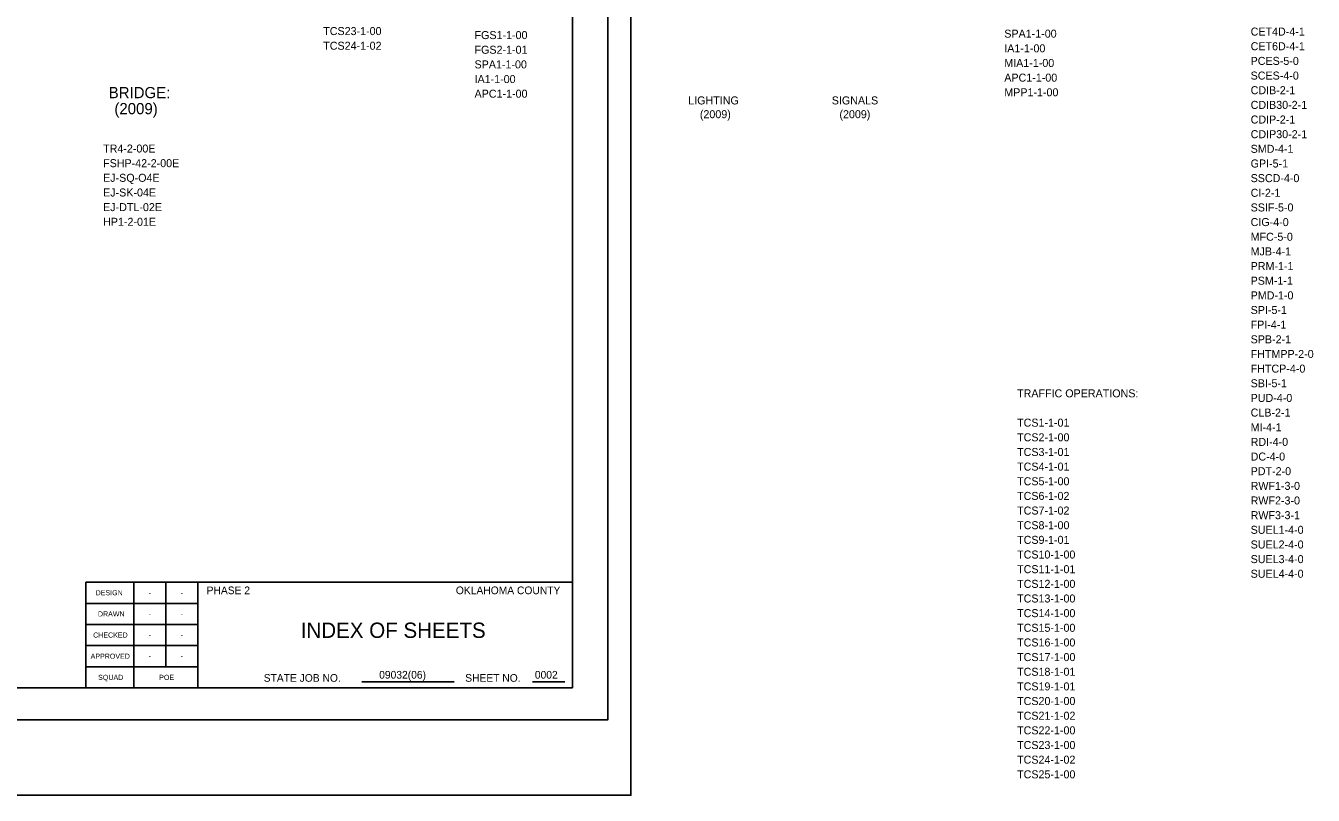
# Model space of a CAD drawing. Extents: x 11.3 to 109.4, y -18.4 to 58.
# Drawn here: x 64.37 to 104.58, y 9.98 to 34 of the extents above; entities that cross this region are included whole.
import ezdxf

# ---------------------------------------------------------------- set-up
doc = ezdxf.new("R2010")
doc.units = 0
for name, color, linetype in [('PR_Improvements_Txt', 7, 'Continuous'), ('SHT_Plot_Shape_Full', 7, 'Continuous'), ('SHT_Plot_Shape_Half', 7, 'Continuous'), ('SHT_Sheet_Border', 7, 'Continuous'), ('SHT_Standard_Sheet_Lines', 7, 'Continuous'), ('SHT_Standard_Sheet_Txt', 7, 'Continuous')]:
    doc.layers.add(name, color=color, linetype=linetype)

msp = doc.modelspace()

# ---------------------------------------------------------------- linework, layer by layer
at = {"layer": 'SHT_Plot_Shape_Full'}
msp.add_lwpolyline([(11.276, 57.98), (83.276, 57.98), (83.276, 9.98), (11.276, 9.98)], close=True, dxfattribs=at)
at = {"layer": 'SHT_Plot_Shape_Half'}
msp.add_lwpolyline([(14.551, 56.33), (82.551, 56.33), (82.551, 12.33), (14.551, 12.33)], close=True, dxfattribs=at)
at = {"layer": 'SHT_Sheet_Border'}
for p, q in [((66.251, 13.33), (66.251, 16.63)), ((66.251, 16.63), (81.451, 16.63)), ((69.751, 13.33), (69.751, 16.632))]:
    msp.add_line(p, q, dxfattribs=at)
msp.add_lwpolyline([(81.451, 13.33), (18.451, 13.33), (18.451, 55.33), (81.451, 55.33)], close=True, dxfattribs=at)
at = {"layer": 'SHT_Standard_Sheet_Lines'}
for p, q in [((67.751, 13.33), (67.751, 16.632)), ((68.751, 13.991), (68.751, 16.632)), ((74.873, 13.523), (77.753, 13.523)), ((80.202, 13.523), (81.207, 13.523))]:
    msp.add_line(p, q, dxfattribs=at)
for points in [[(69.751, 15.97), (66.251, 15.97)], [(69.751, 15.31), (66.251, 15.31)], [(69.751, 14.65), (66.251, 14.65)], [(69.751, 13.99), (66.251, 13.99)]]:
    msp.add_lwpolyline(points, dxfattribs=at)

# ---------------------------------------------------------------- texts
at = {"layer": 'PR_Improvements_Txt'}
for s, height, p in [('TCS23-1-00', 0.25, (73.664, 33.712)), ('FGS1-1-00', 0.25, (78.39, 33.587)), ('SPA1-1-00', 0.25, (94.935, 33.631)), ('CET4D-4-1', 0.25, (102.629, 33.696)), ('TCS24-1-02', 0.25, (73.664, 33.254)), ('FGS2-1-01', 0.25, (78.39, 33.129)), ('IA1-1-00', 0.25, (94.935, 33.173)), ('CET6D-4-1', 0.25, (102.629, 33.238)), ('PCES-5-0', 0.25, (102.629, 32.781)), ('SPA1-1-00', 0.25, (78.39, 32.672)), ('MIA1-1-00', 0.25, (94.935, 32.716)), ('SCES-4-0', 0.25, (102.629, 32.323)), ('IA1-1-00', 0.25, (78.39, 32.214)), ('APC1-1-00', 0.25, (94.935, 32.258)), ('BRIDGE:', 0.35, (66.964, 31.741)), ('APC1-1-00', 0.25, (78.39, 31.757)), ('LIGHTING', 0.25, (85.065, 31.547)), ('SIGNALS', 0.25, (89.547, 31.547)), ('MPP1-1-00', 0.25, (94.935, 31.801)), ('CDIB-2-1', 0.25, (102.629, 31.866)), ('(2009)', 0.35, (67.142, 31.241)), ('(2009)', 0.25, (85.427, 31.117)), ('(2009)', 0.25, (89.786, 31.117)), ('CDIB30-2-1', 0.25, (102.629, 31.408)), ('CDIP-2-1', 0.25, (102.629, 30.951)), ('CDIP30-2-1', 0.25, (102.629, 30.493)), ('TR4-2-00E', 0.25, (66.789, 30.045)), ('SMD-4-1', 0.25, (102.629, 30.036)), ('FSHP-42-2-00E', 0.25, (66.789, 29.588)), ('GPI-5-1', 0.25, (102.629, 29.578)), ('EJ-SQ-O4E', 0.25, (66.789, 29.131)), ('SSCD-4-0', 0.25, (102.629, 29.121)), ('EJ-SK-04E', 0.25, (66.789, 28.673)), ('CI-2-1', 0.25, (102.629, 28.663)), ('EJ-DTL-02E', 0.25, (66.789, 28.216)), ('SSIF-5-0', 0.25, (102.629, 28.206)), ('HP1-2-01E', 0.25, (66.789, 27.758)), ('CIG-4-0', 0.25, (102.629, 27.749)), ('MFC-5-0', 0.25, (102.629, 27.291)), ('MJB-4-1', 0.25, (102.629, 26.834)), ('PRM-1-1', 0.25, (102.629, 26.376)), ('PSM-1-1', 0.25, (102.629, 25.919)), ('PMD-1-0', 0.25, (102.629, 25.461)), ('SPI-5-1', 0.25, (102.629, 25.004)), ('FPI-4-1', 0.25, (102.629, 24.546)), ('SPB-2-1', 0.25, (102.629, 24.089)), ('FHTMPP-2-0', 0.25, (102.629, 23.631)), ('FHTCP-4-0', 0.25, (102.629, 23.174)), ('SBI-5-1', 0.25, (102.629, 22.717)), ('TRAFFIC OPERATIONS:', 0.25, (95.335, 22.402)), ('PUD-4-0', 0.25, (102.629, 22.259)), ('TCS1-1-01', 0.25, (95.335, 21.487)), ('CLB-2-1', 0.25, (102.629, 21.802)), ('MI-4-1', 0.25, (102.629, 21.344)), ('TCS2-1-00', 0.25, (95.335, 21.03)), ('RDI-4-0', 0.25, (102.629, 20.887)), ('TCS3-1-01', 0.25, (95.335, 20.572)), ('DC-4-0', 0.25, (102.629, 20.429)), ('TCS4-1-01', 0.25, (95.335, 20.115)), ('PDT-2-0', 0.25, (102.629, 19.972)), ('TCS5-1-00', 0.25, (95.335, 19.657)), ('RWF1-3-0', 0.25, (102.629, 19.514)), ('TCS6-1-02', 0.25, (95.335, 19.2)), ('RWF2-3-0', 0.25, (102.629, 19.057)), ('TCS7-1-02', 0.25, (95.335, 18.743)), ('TCS8-1-00', 0.25, (95.335, 18.285)), ('RWF3-3-1', 0.25, (102.629, 18.599)), ('SUEL1-4-0', 0.25, (102.629, 18.142)), ('TCS9-1-01', 0.25, (95.335, 17.828)), ('SUEL2-4-0', 0.25, (102.629, 17.684)), ('TCS10-1-00', 0.25, (95.335, 17.37)), ('SUEL3-4-0', 0.25, (102.629, 17.227)), ('TCS11-1-01', 0.25, (95.335, 16.913)), ('SUEL4-4-0', 0.25, (102.629, 16.77)), ('TCS12-1-00', 0.25, (95.335, 16.455)), ('TCS13-1-00', 0.25, (95.335, 15.998)), ('TCS14-1-00', 0.25, (95.335, 15.54)), ('TCS15-1-00', 0.25, (95.335, 15.083)), ('TCS16-1-00', 0.25, (95.335, 14.625)), ('TCS17-1-00', 0.25, (95.335, 14.168)), ('TCS18-1-01', 0.25, (95.335, 13.71)), ('TCS19-1-01', 0.25, (95.335, 13.253)), ('TCS20-1-00', 0.25, (95.335, 12.796)), ('TCS21-1-02', 0.25, (95.335, 12.338)), ('TCS22-1-00', 0.25, (95.335, 11.881)), ('TCS23-1-00', 0.25, (95.335, 11.423)), ('TCS24-1-02', 0.25, (95.335, 10.966)), ('TCS25-1-00', 0.25, (95.335, 10.508))]:
    msp.add_text(s, height=height, dxfattribs=at).set_placement(p)
at = {"layer": 'SHT_Standard_Sheet_Txt'}
for s, p in [('PHASE 2', (70.022, 16.257)), ('OKLAHOMA COUNTY', (77.807, 16.257))]:
    msp.add_text(s, height=0.24, rotation=0, dxfattribs=at).set_placement(p)
for s, height, p in [('DESIGN', 0.16, (66.555, 16.222)), ('-', 0.16, (68.212, 16.222)), ('-', 0.16, (69.212, 16.222)), ('DRAWN', 0.16, (66.627, 15.561)), ('-', 0.16, (68.212, 15.561)), ('-', 0.16, (69.212, 15.561)), ('INDEX OF SHEETS', 0.48, (72.96, 14.891)), ('CHECKED', 0.16, (66.477, 14.901)), ('-', 0.16, (68.212, 14.901)), ('-', 0.16, (69.212, 14.901)), ('APPROVED', 0.16, (66.398, 14.241)), ('-', 0.16, (68.212, 14.241)), ('-', 0.16, (69.212, 14.241)), ('SQUAD', 0.16, (66.634, 13.58)), ('POE', 0.16, (68.541, 13.58)), ('STATE JOB NO.', 0.24, (71.805, 13.523)), ('09032(06)', 0.24, (75.411, 13.621)), ('SHEET NO. ', 0.24, (78.098, 13.523)), ('0002', 0.24, (80.273, 13.621))]:
    msp.add_text(s, height=height, dxfattribs=at).set_placement(p)

doc.saveas('drawing.dxf')
